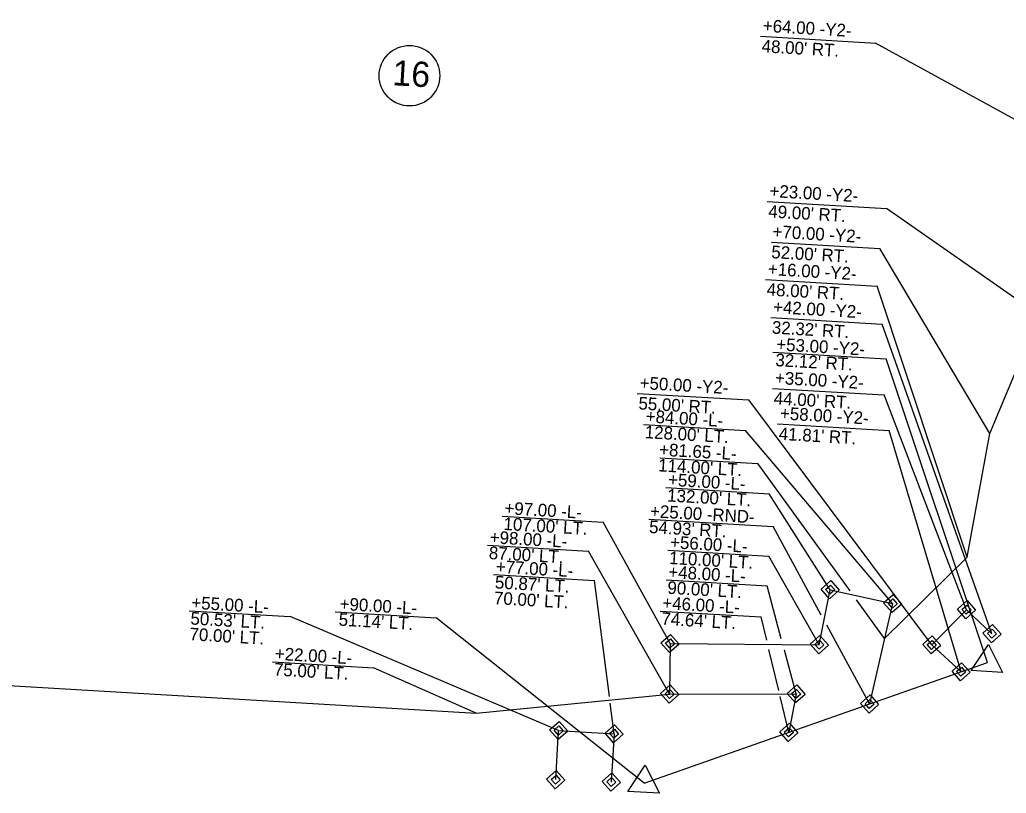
# Model space of a CAD drawing. Extents: x 2010883 to 2014849, y 442000 to 447413.
# Drawn here: x 2012782.2 to 2013172.7, y 444974.4 to 445280.7 of the extents above; entities that cross this region are included whole.
import ezdxf

# ---------------------------------------------------------------- set-up
doc = ezdxf.new("R2010")
doc.units = 0
for name, color, linetype in [('Prop Easement Construction', 7, 'Continuous'), ('Prop Easement Construction Station Offsets', 7, 'Continuous'), ('Prop Easement Permanent Drainage', 7, 'Continuous'), ('Prop Easement Permanent Drainage Station Offsets', 7, 'Continuous'), ('Prop Easement Permanent Utility', 7, 'Continuous'), ('Prop Easement Permanent Utility Station Offsets', 7, 'Continuous'), ('Prop Parcel Number CELL', 7, 'Continuous'), ('Prop Parcel Number Text', 7, 'Continuous'), ('Prop ROW Marker CELL', 7, 'Continuous'), ('Prop ROW Permanent Easement CELL', 7, 'Continuous'), ('Prop ROW RW Lines', 7, 'Continuous'), ('Prop ROW Station Offsets', 7, 'Continuous')]:
    doc.layers.add(name, color=color, linetype=linetype)

msp = doc.modelspace()

# ---------------------------------------------------------------- linework, layer by layer
at = {"layer": 'Prop Easement Construction'}
for p, q in [((2013166.15, 445116.84), (2013185.64, 445163.8)), ((2013157.23, 445067.85), (2013166.15, 445116.84)), ((2013124.51, 445035.71), (2013157.23, 445067.85)), ((2012673.34, 445023.24), (2012962.84, 445006.17)), ((2012962.84, 445006.17), (2013039.42, 445013.68))]:
    msp.add_line(p, q, dxfattribs=at)
at = {"layer": 'Prop Easement Construction Station Offsets'}
for p, q in [((2013075.38, 445274.19), (2013120.91, 445271.5)), ((2013212.33, 445221.34), (2013120.91, 445271.5)), ((2013078.03, 445208.76), (2013125.32, 445205.97)), ((2013185.64, 445163.8), (2013125.32, 445205.97)), ((2013079.75, 445192.6), (2013122.68, 445190.07)), ((2013166.15, 445116.84), (2013122.68, 445190.07)), ((2013077.38, 445177.86), (2013121.53, 445175.26)), ((2013157.23, 445067.85), (2013121.53, 445175.26)), ((2013035.59, 445107.25), (2013074.34, 445104.97)), ((2013110.81, 445054.62), (2013074.34, 445104.97)), ((2013124.51, 445035.71), (2013113.44, 445050.98)), ((2012882.28, 445026.43), (2012922.21, 445024.07)), ((2012962.84, 445006.17), (2012922.21, 445024.07))]:
    msp.add_line(p, q, dxfattribs=at)
at = {"layer": 'Prop Easement Permanent Drainage'}
for p, q in [((2013143.16, 445033.15), (2013156.91, 445047.07)), ((2013166.99, 445037.59), (2013156.91, 445047.07)), ((2013154.77, 445022.5), (2013143.16, 445033.15)), ((2012994.34, 444979.8), (2012995.49, 444999.24)), ((2012995.49, 444999.24), (2013017.45, 444997.94)), ((2013017.45, 444997.94), (2013016.33, 444978.84))]:
    msp.add_line(p, q, dxfattribs=at)
at = {"layer": 'Prop Easement Permanent Drainage Station Offsets'}
for p, q in [((2013079.43, 445162.79), (2013123.58, 445160.19)), ((2013166.99, 445037.59), (2013123.58, 445160.19)), ((2013026.62, 445132.76), (2013070.77, 445130.16)), ((2013080.19, 445134.75), (2013124.34, 445132.15)), ((2013156.91, 445047.07), (2013124.34, 445132.15)), ((2013143.16, 445033.15), (2013070.77, 445130.16)), ((2013082.16, 445120.7), (2013126.31, 445118.1)), ((2013154.77, 445022.5), (2013126.31, 445118.1)), ((2012969.75, 445061), (2013009.68, 445058.65)), ((2013015.56, 445012.71), (2013009.68, 445058.65)), ((2012849.25, 445046.7), (2012889.18, 445044.35)), ((2012995.49, 444999.24), (2012889.18, 445044.35)), ((2013017.45, 444997.94), (2013015.9, 445010.06))]:
    msp.add_line(p, q, dxfattribs=at)
at = {"layer": 'Prop Easement Permanent Utility'}
for p, q in [((2013098.67, 445033.22), (2013102.96, 445055.01)), ((2013102.96, 445055.01), (2013127.68, 445049.55)), ((2013127.68, 445049.55), (2013118.55, 445009.76)), ((2013039.59, 445033.7), (2013039.42, 445013.68)), ((2013039.59, 445033.7), (2013098.67, 445033.22)), ((2013039.42, 445013.68), (2013089.51, 445013.73)), ((2013089.51, 445013.73), (2013086.6, 444998.51))]:
    msp.add_line(p, q, dxfattribs=at)
at = {"layer": 'Prop Easement Permanent Utility Station Offsets'}
for p, q in [((2013029.08, 445120.49), (2013069.51, 445118.1)), ((2013127.68, 445049.55), (2013069.51, 445118.1)), ((2013037.94, 445095.42), (2013078.86, 445093.01)), ((2013102.96, 445055.01), (2013078.86, 445093.01)), ((2012973.16, 445084.15), (2013013.09, 445081.79)), ((2013039.59, 445033.7), (2013013.09, 445081.79)), ((2013031.2, 445082.93), (2013080.38, 445080.03)), ((2013099.46, 445044.91), (2013080.38, 445080.03)), ((2012967.35, 445072.64), (2013007.28, 445070.29)), ((2013039.42, 445013.68), (2013007.28, 445070.29)), ((2013038.72, 445070.66), (2013078.68, 445068.3)), ((2013098.67, 445033.22), (2013078.68, 445068.3)), ((2013038.03, 445058.88), (2013077.99, 445056.52)), ((2013083.63, 445035.55), (2013077.99, 445056.52)), ((2013035.66, 445046.57), (2013075.62, 445044.22)), ((2013077.84, 445034.98), (2013075.62, 445044.22)), ((2013118.55, 445009.76), (2013101.63, 445040.91)), ((2013082.61, 445015.14), (2013078.71, 445031.36)), ((2013089.51, 445013.73), (2013084.83, 445031.08)), ((2013086.6, 444998.51), (2013083.19, 445012.72))]:
    msp.add_line(p, q, dxfattribs=at)
at = {"layer": 'Prop Parcel Number CELL'}
msp.add_line((2012936.45, 445258.57), (2012936.45, 445258.57), dxfattribs=at)
msp.add_circle((2012936.45, 445258.57), 12, dxfattribs=at)
at = {"layer": 'Prop ROW Marker CELL'}
for p, q in [((2013102.96, 445055.01), (2013102.96, 445055.01)), ((2013127.68, 445049.55), (2013127.68, 445049.55)), ((2013156.91, 445047.07), (2013156.91, 445047.07)), ((2013166.99, 445037.59), (2013166.99, 445037.59)), ((2013039.59, 445033.7), (2013039.59, 445033.7)), ((2013098.67, 445033.22), (2013098.67, 445033.22)), ((2013143.16, 445033.15), (2013143.16, 445033.15)), ((2013165.19, 445026.17), (2013165.19, 445026.17)), ((2013154.77, 445022.5), (2013154.77, 445022.5)), ((2013039.42, 445013.68), (2013039.42, 445013.68)), ((2013089.51, 445013.73), (2013089.51, 445013.73)), ((2013118.55, 445009.76), (2013118.55, 445009.76)), ((2012995.49, 444999.24), (2012995.49, 444999.24)), ((2013086.6, 444998.51), (2013086.6, 444998.51)), ((2013017.45, 444997.94), (2013017.45, 444997.94)), ((2012994.34, 444979.8), (2012994.34, 444979.8)), ((2013016.33, 444978.84), (2013016.33, 444978.84)), ((2013029.32, 444978.34), (2013029.32, 444978.34))]:
    msp.add_line(p, q, dxfattribs=at)
for points in [[(2013158.74, 445022.95), (2013165.61, 445033.36), (2013171.21, 445022.21)], [(2013022.87, 444975.12), (2013029.74, 444985.53), (2013035.35, 444974.38)]]:
    msp.add_lwpolyline(points, close=True, dxfattribs=at)
at = {"layer": 'Prop ROW Permanent Easement CELL'}
for points in [[(2013103.17, 445058.6), (2013106.55, 445054.8), (2013102.75, 445051.42), (2013099.36, 445055.22)], [(2013103.06, 445056.81), (2013104.75, 445054.9), (2013102.85, 445053.21), (2013101.16, 445055.12)], [(2013127.89, 445053.14), (2013131.27, 445049.33), (2013127.47, 445045.95), (2013124.09, 445049.76)], [(2013127.78, 445051.34), (2013129.48, 445049.44), (2013127.57, 445047.75), (2013125.88, 445049.65)], [(2013157.12, 445050.67), (2013160.5, 445046.86), (2013156.7, 445043.48), (2013153.32, 445047.29)], [(2013157.02, 445048.87), (2013158.71, 445046.97), (2013156.8, 445045.28), (2013155.11, 445047.18)], [(2013167.2, 445041.19), (2013170.59, 445037.38), (2013166.78, 445034), (2013163.4, 445037.81)], [(2013167.1, 445039.39), (2013168.79, 445037.49), (2013166.89, 445035.8), (2013165.19, 445037.7)], [(2013039.81, 445037.29), (2013043.19, 445033.49), (2013039.38, 445030.11), (2013036, 445033.91)], [(2013039.7, 445035.5), (2013041.39, 445033.6), (2013039.49, 445031.9), (2013037.8, 445033.81)], [(2013098.88, 445036.82), (2013102.26, 445033.01), (2013098.46, 445029.63), (2013095.07, 445033.44)], [(2013098.77, 445035.02), (2013100.47, 445033.12), (2013098.56, 445031.43), (2013096.87, 445033.33)], [(2013143.38, 445036.75), (2013146.76, 445032.94), (2013142.95, 445029.56), (2013139.57, 445033.37)], [(2013143.27, 445034.95), (2013144.96, 445033.05), (2013143.06, 445031.36), (2013141.37, 445033.26)], [(2013154.98, 445026.1), (2013158.36, 445022.29), (2013154.56, 445018.91), (2013151.18, 445022.72)], [(2013154.88, 445024.3), (2013156.57, 445022.4), (2013154.66, 445020.71), (2013152.97, 445022.61)], [(2013039.63, 445017.27), (2013043.01, 445013.47), (2013039.2, 445010.08), (2013035.82, 445013.89)], [(2013039.52, 445015.47), (2013041.21, 445013.57), (2013039.31, 445011.88), (2013037.62, 445013.78)], [(2013089.72, 445017.32), (2013093.1, 445013.52), (2013089.29, 445010.14), (2013085.91, 445013.94)], [(2013089.61, 445015.53), (2013091.3, 445013.62), (2013089.4, 445011.93), (2013087.71, 445013.84)], [(2013118.76, 445013.35), (2013122.15, 445009.54), (2013118.34, 445006.16), (2013114.96, 445009.97)], [(2013118.66, 445011.55), (2013120.35, 445009.65), (2013118.45, 445007.96), (2013116.76, 445009.86)], [(2012995.7, 445002.83), (2012999.08, 444999.02), (2012995.28, 444995.64), (2012991.9, 444999.45)], [(2012995.6, 445001.03), (2012997.29, 444999.13), (2012995.38, 444997.44), (2012993.69, 444999.34)], [(2013017.66, 445001.54), (2013021.04, 444997.73), (2013017.24, 444994.35), (2013013.86, 444998.15)], [(2013017.56, 444999.74), (2013019.25, 444997.84), (2013017.35, 444996.15), (2013015.65, 444998.05)], [(2013086.82, 445002.1), (2013090.2, 444998.3), (2013086.39, 444994.92), (2013083.01, 444998.72)], [(2013086.71, 445000.31), (2013088.4, 444998.4), (2013086.5, 444996.71), (2013084.81, 444998.62)], [(2012994.56, 444983.39), (2012997.94, 444979.59), (2012994.13, 444976.21), (2012990.75, 444980.01)], [(2012994.45, 444981.6), (2012996.14, 444979.69), (2012994.24, 444978), (2012992.55, 444979.9)], [(2013016.54, 444982.44), (2013019.92, 444978.63), (2013016.11, 444975.25), (2013012.73, 444979.06)], [(2013016.43, 444980.64), (2013018.12, 444978.74), (2013016.22, 444977.05), (2013014.53, 444978.95)]]:
    msp.add_lwpolyline(points, close=True, dxfattribs=at)
at = {"layer": 'Prop ROW RW Lines'}
msp.add_line((2013029.32, 444978.34), (2013165.19, 445026.17), dxfattribs=at)
at = {"layer": 'Prop ROW Station Offsets'}
for p, q in [((2013080.25, 445149.14), (2013125.17, 445146.49)), ((2013165.19, 445026.17), (2013125.17, 445146.49)), ((2012907.11, 445046.28), (2012947.04, 445043.93)), ((2013029.32, 444978.34), (2012947.04, 445043.93))]:
    msp.add_line(p, q, dxfattribs=at)

# ---------------------------------------------------------------- texts
at = {"layer": 'Prop Easement Construction Station Offsets'}
for s, p in [('+64.00 -Y2-', (2013076.21, 445275.97)), ("48.00' RT.", (2013075.73, 445267.86)), ('+23.00 -Y2-', (2013078.86, 445210.54)), ("49.00' RT.", (2013078.38, 445202.43)), ('+70.00 -Y2-', (2013080.05, 445194.45)), ("52.00' RT.", (2013079.57, 445186.34)), ('+16.00 -Y2-', (2013078.21, 445179.65)), ("48.00' RT.", (2013077.73, 445171.54)), ('+81.65 -L-', (2013035.17, 445108.13)), ("114.00' LT.", (2013034.8, 445101.89)), ('+22.00 -L-', (2012883.06, 445027.28)), ("75.00' LT.", (2012882.69, 445021.04))]:
    msp.add_text(s, height=5, rotation=356.6264, dxfattribs=at).set_placement(p)
at = {"layer": 'Prop Easement Permanent Drainage Station Offsets'}
for s, p in [('+42.00 -Y2-', (2013080.26, 445164.58)), ("32.32' RT.", (2013079.78, 445156.47)), ('+50.00 -Y2-', (2013027.45, 445134.54)), ('+35.00 -Y2-', (2013081.02, 445136.54)), ("55.00' RT.", (2013026.97, 445126.43)), ("44.00' RT.", (2013080.54, 445128.42)), ('+58.00 -Y2-', (2013082.99, 445122.49)), ("41.81' RT.", (2013082.52, 445114.38)), ('+77.00 -L-', (2012970.52, 445061.78)), ("50.87' LT.", (2012970.16, 445055.54)), ("70.00' LT.", (2012969.79, 445049.3)), ('+55.00 -L-', (2012850.02, 445047.48)), ("50.53' LT.", (2012849.66, 445041.24)), ("70.00' LT.", (2012849.29, 445035))]:
    msp.add_text(s, height=5, rotation=356.6264, dxfattribs=at).set_placement(p)
at = {"layer": 'Prop Easement Permanent Utility Station Offsets'}
for s, p in [('+84.00 -L-', (2013029.85, 445121.27)), ("128.00' LT.", (2013029.48, 445115.03)), ('+59.00 -L-', (2013038.71, 445096.2)), ("132.00' LT.", (2013038.35, 445089.96)), ('+97.00 -L-', (2012973.93, 445084.93)), ('+25.00 -RND-', (2013031.56, 445083.73)), ("107.00' LT.", (2012973.57, 445078.69)), ("54.93' RT.", (2013031.19, 445077.49)), ('+98.00 -L-', (2012968.12, 445073.42)), ('+56.00 -L-', (2013039.49, 445071.44)), ("87.00' LT.", (2012967.75, 445067.18)), ("110.00' LT.", (2013039.12, 445065.2)), ('+48.00 -L-', (2013038.8, 445059.65)), ("90.00' LT.", (2013038.43, 445053.41)), ('+46.00 -L-', (2013036.43, 445047.35)), ("74.64' LT.", (2013036.07, 445041.11))]:
    msp.add_text(s, height=5, rotation=356.6264, dxfattribs=at).set_placement(p)
at = {"layer": 'Prop Parcel Number Text'}
msp.add_text('16', height=10, rotation=356.6264, dxfattribs=at).set_placement((2012929.5, 445254.82))
at = {"layer": 'Prop ROW Station Offsets'}
for s, p in [('+53.00 -Y2-', (2013081.53, 445149.81)), ("32.12' RT.", (2013081.16, 445143.58)), ('+90.00 -L-', (2012908.7, 445047.03)), ("51.14' LT.", (2012908.33, 445040.79))]:
    msp.add_text(s, height=5, rotation=356.6264, dxfattribs=at).set_placement(p)

doc.saveas('drawing.dxf')
